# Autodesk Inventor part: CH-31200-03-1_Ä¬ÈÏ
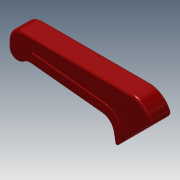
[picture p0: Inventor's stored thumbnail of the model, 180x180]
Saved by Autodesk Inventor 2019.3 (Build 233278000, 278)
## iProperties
Created: 2010-06
Part Number: CH-31200-03-1_Ä¬ÈÏ
Material: Ogólny
Document SubType Name: Modeling
Designer: CADENGINEERING4
Density: 1 g/cm^3
Appearance: Czerwona
Author: CADENGINEERING4
Revision Number: ÈÎºÎ
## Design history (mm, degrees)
feature "NONE"
node "Bryła1"
